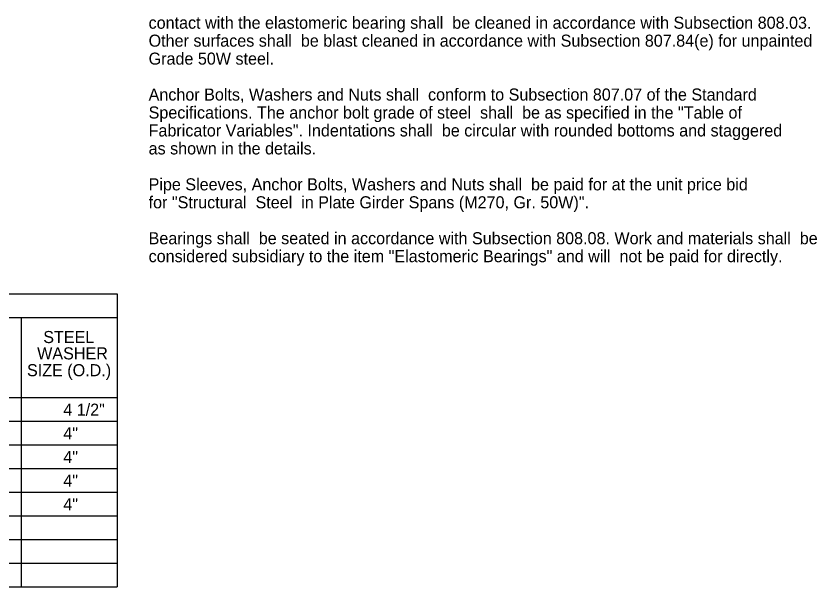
# Model space of a CAD drawing. Extents: x -194 to 226, y 505 to 725.
# Drawn here: x 47.6 to 130.7, y 542.1 to 601.3 of the extents above; entities that cross this region are included whole.
import ezdxf

# ---------------------------------------------------------------- set-up
doc = ezdxf.new("R2010")
doc.units = 0
doc.layers.add('Level 40', color=7, linetype='Continuous')
doc.layers.add('Level 41', color=7, linetype='Continuous')

msp = doc.modelspace()

# ---------------------------------------------------------------- linework, layer by layer
at = {"layer": 'Level 40'}
for p, q in [((48.111, 570.011), (48.111, 542.092)), ((-173.559, 561.719), (58.082, 561.719)), ((48.111, 562.218), (48.111, 558.728)), ((-173.559, 559.266), (58.082, 559.266)), ((-173.559, 556.812), (58.082, 556.812)), ((-173.559, 556.812), (58.082, 556.812)), ((-173.559, 554.359), (58.082, 554.359)), ((-173.559, 554.359), (58.082, 554.359)), ((-173.559, 551.906), (58.082, 551.906)), ((-173.559, 551.905), (58.082, 551.905)), ((-173.559, 549.452), (58.082, 549.452)), ((-173.559, 546.999), (58.082, 546.999)), ((-173.559, 544.545), (58.082, 544.545))]:
    msp.add_line(p, q, dxfattribs=at)
at = {"layer": 'Level 41'}
for p, q in [((-92.484, 572.464), (58.082, 572.464)), ((58.082, 572.464), (58.082, 542.092)), ((-173.559, 570.011), (58.082, 570.011)), ((-173.559, 542.092), (58.082, 542.092))]:
    msp.add_line(p, q, dxfattribs=at)

# ---------------------------------------------------------------- texts
at = {"layer": 'Level 40'}
for s, p in [('contact with the elastomeric bearing shall  be cleaned in accordance with Subsection 808.03.', (61.341, 599.956)), ('Other surfaces shall  be blast cleaned in accordance with Subsection 807.84(e) for unpainted', (61.341, 598.094)), ('Grade 50W steel.', (61.341, 596.233)), ('Anchor Bolts, Washers and Nuts shall  conform to Subsection 807.07 of the Standard', (61.341, 592.51)), ('Specifications. The anchor bolt grade of steel  shall  be as specified in the "Table of', (61.341, 590.648)), ('Fabricator Variables". Indentations shall  be circular with rounded bottoms and staggered', (61.341, 588.787)), ('as shown in the details.', (61.341, 586.925)), ('Pipe Sleeves, Anchor Bolts, Washers and Nuts shall  be paid for at the unit price bid', (61.341, 583.202)), ('for "Structural  Steel  in Plate Girder Spans (M270, Gr. 50W)".', (61.341, 581.34)), ('Bearings shall  be seated in accordance with Subsection 808.08. Work and materials shall  be', (61.341, 577.617)), ('considered subsidiary to the item "Elastomeric Bearings" and will  not be paid for directly.', (61.341, 575.756)), ('STEEL', (50.41, 567.375)), ('WASHER', (49.777, 565.682)), ('SIZE (O.D.)', (48.725, 563.937)), ('4 1/2"', (52.49, 559.846)), ('4"', (52.49, 557.392)), ('4"', (52.49, 554.939)), ('4"', (52.49, 552.485)), ('4"', (52.49, 550.032))]:
    msp.add_text(s, height=1.25, dxfattribs=at).set_placement(p)

doc.saveas('drawing.dxf')
